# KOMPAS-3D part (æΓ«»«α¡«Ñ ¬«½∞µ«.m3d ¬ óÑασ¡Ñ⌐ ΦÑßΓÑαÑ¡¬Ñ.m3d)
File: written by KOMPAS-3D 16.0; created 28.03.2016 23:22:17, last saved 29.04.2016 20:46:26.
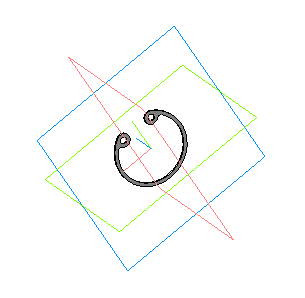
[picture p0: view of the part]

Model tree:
1. Эскиз:1
2. Операция выдавливания:1
     Расстояние 1 = 0.5
3. Скругление:1
     Радиус = 1
4. Скругление:2
     Радиус = 1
